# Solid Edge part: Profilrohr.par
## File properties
Username: bmolnar
Dokumentum tartalom típus: 0
Author: bmolnar
Last saved by: bmolnar
Revision: 95
Sűrűség: 0,000 kg/m^3
Pontosság: 0,990
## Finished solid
Body 1: solid body, 115 faces, 338 edges, 224 vertices.
  Faces by surface: cylinder 59, plane 56
  Edges by curve: line 220, circle 118
Bounding box of the edges (mm): 113.500 x 113.500 x 348.000, from (-56.75, -56.75, -331.5) to (56.75, 56.75, 16.5).
Cylindrical faces by radius (mm): R0.15 x24, R0.25 x24, R1 x4, R12.25 x4, R35 x2, R50 x1
Planar faces by outward normal: +x 13, +y 14, +z 1, -x 13, -y 14, -z 1
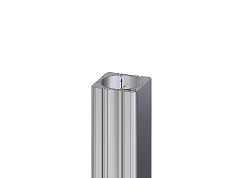
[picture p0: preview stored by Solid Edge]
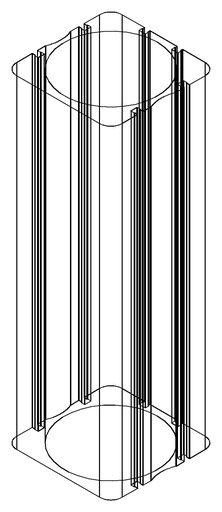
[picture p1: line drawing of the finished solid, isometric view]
